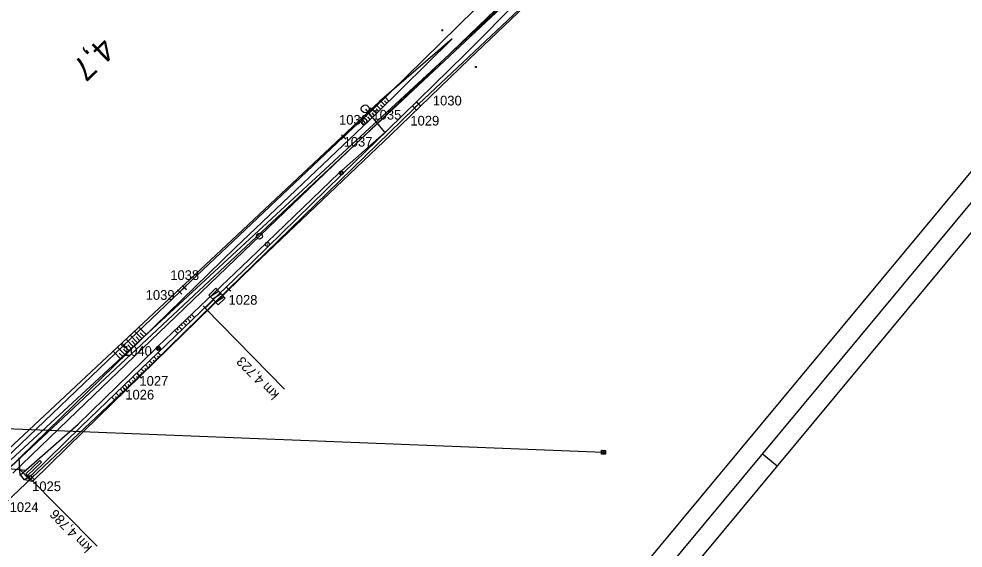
# Model space of a CAD drawing. Extents: x -738085 to -734426, y -1122197 to -1119748.
# Drawn here: x -737687.7 to -737444.6, y -1121801.5 to -1121665.2 of the extents above; entities that cross this region are included whole.
import ezdxf

# ---------------------------------------------------------------- set-up
doc = ezdxf.new("R2010")
doc.units = 0
for name, color, linetype in [('SŽDC', 7, 'Continuous'), ('Vrstva 1', 7, 'Continuous'), ('Vrstva 11', 7, 'Continuous'), ('Vrstva 12', 7, 'Continuous'), ('Vrstva 19', 7, 'Continuous'), ('Vrstva 25', 7, 'Continuous'), ('Vrstva 36', 7, 'Continuous'), ('Vrstva 4', 7, 'Continuous'), ('Vrstva 43', 7, 'Continuous'), ('Vrstva 48', 7, 'Continuous'), ('Vrstva 49', 7, 'Continuous'), ('Vrstva 60', 7, 'Continuous'), ('Vrstva 63', 7, 'Continuous'), ('Vrstva 7', 7, 'Continuous'), ('Vrstva 9', 7, 'Continuous')]:
    doc.layers.add(name, color=color, linetype=linetype)

msp = doc.modelspace()

# ---------------------------------------------------------------- linework, layer by layer
at = {"layer": 'SŽDC'}
for p, q in [((-737585.89, -1121688.17), (-737633.76, -1121734.81)), ((-737599.36, -1121691.09), (-737596.72, -1121688.63)), ((-737604.14, -1121695.61), (-737599.36, -1121691.09)), ((-737645.15, -1121734.39), (-737604.14, -1121695.61)), ((-737633.76, -1121734.81), (-737656.71, -1121757.17)), ((-737696.93, -1121783.83), (-737660.95, -1121749.48)), ((-737684.33, -1121783.29), (-737691.03, -1121789.69))]:
    msp.add_line(p, q, dxfattribs=at)
for points in [[(-737596.72, -1121688.63), (-737552.76, -1121645.44), (-737544, -1121633.28)], [(-737548.98, -1121653.36), (-737584.84, -1121687.15), (-737585.89, -1121688.17)], [(-737660.95, -1121749.48), (-737646.34, -1121735.52), (-737645.15, -1121734.39)], [(-737656.71, -1121757.17), (-737660.35, -1121760.72), (-737684.33, -1121783.29)]]:
    msp.add_lwpolyline(points, dxfattribs=at)
at = {"layer": 'Vrstva 1'}
msp.add_line((-737496.36, -1121777.15), (-737492.52, -1121780.34), dxfattribs=at)
for points in [[(-737452.56, -1121267.51), (-737989.34, -1121913.61), (-737760.91, -1122103.4), (-737224.12, -1121457.29)], [(-737982.3, -1121912.96), (-737451.91, -1121274.55), (-737231.17, -1121457.94), (-737761.56, -1122096.35)], [(-737451.26, -1121281.58), (-737844.27, -1121754.63), (-737631.21, -1121931.64), (-737238.2, -1121458.59)]]:
    msp.add_lwpolyline(points, close=True, dxfattribs=at)
for points in [[(-737505.35, -1121528.98), (-737507.02, -1121535.76), (-737508.18, -1121541.1), (-737509.7, -1121548.87), (-737511.05, -1121556.54), (-737512.45, -1121564.46), (-737514.07, -1121573.14), (-737515.6, -1121580.26), (-737517.59, -1121588.18), (-737519.85, -1121595.56), (-737522.41, -1121602.65), (-737525.26, -1121609.39), (-737528.71, -1121616.54), (-737532.49, -1121623.46), (-737535.97, -1121629.07), (-737539.35, -1121634.1), (-737544.33, -1121640.72), (-737549.2, -1121646.51), (-737554.12, -1121651.88), (-737559.65, -1121657.52), (-737565.05, -1121662.86), (-737573.92, -1121671.42), (-737588.06, -1121684.98)], [(-737505.35, -1121528.98), (-737507.02, -1121535.76), (-737508.18, -1121541.1), (-737509.7, -1121548.87), (-737511.05, -1121556.54), (-737512.45, -1121564.46), (-737514.07, -1121573.14), (-737515.6, -1121580.26), (-737517.59, -1121588.18), (-737519.85, -1121595.56), (-737522.41, -1121602.65), (-737525.26, -1121609.39), (-737528.71, -1121616.54), (-737532.49, -1121623.46), (-737535.97, -1121629.07), (-737539.35, -1121634.1), (-737544.33, -1121640.72), (-737549.2, -1121646.51), (-737554.12, -1121651.88), (-737559.65, -1121657.52), (-737565.05, -1121662.86), (-737573.92, -1121671.42), (-737588.06, -1121684.98)], [(-737588.06, -1121684.98), (-737606.71, -1121702.84), (-737629.82, -1121725.04), (-737653.84, -1121748.12), (-737672.71, -1121766.23), (-737689.31, -1121782.16)], [(-737588.06, -1121684.98), (-737606.71, -1121702.84), (-737629.82, -1121725.04), (-737653.84, -1121748.12), (-737672.71, -1121766.23), (-737689.31, -1121782.16)]]:
    msp.add_lwpolyline(points, dxfattribs=at)
at = {"layer": 'Vrstva 11'}
for p, q in [((-737604.91, -1121704.4), (-737604.93, -1121705.33)), ((-737604.53, -1121704.41), (-737604.55, -1121705.33)), ((-737652.03, -1121749.57), (-737652.05, -1121750.49)), ((-737651.66, -1121749.58), (-737651.68, -1121750.49))]:
    msp.add_line(p, q, dxfattribs=at)
for centre in [(-737604.74, -1121704.87), (-737651.86, -1121750.03)]:
    msp.add_circle(centre, 0.5, dxfattribs=at)
at = {"layer": 'Vrstva 12'}
for p, q in [((-737604.17, -1121704.88), (-737604.75, -1121705.43)), ((-737651.3, -1121750.04), (-737651.88, -1121750.6))]:
    msp.add_line(p, q, dxfattribs=at)
for points in [[(-737605.3, -1121704.85), (-737604.72, -1121704.3), (-737604.17, -1121704.88), (-737604.75, -1121705.43), (-737605.3, -1121704.85)], [(-737605.3, -1121704.85), (-737604.75, -1121705.43), (-737604.75, -1121705.43)], [(-737604.72, -1121704.3), (-737604.17, -1121704.88), (-737604.17, -1121704.88)], [(-737652.43, -1121750.02), (-737651.85, -1121749.47), (-737651.3, -1121750.04), (-737651.88, -1121750.6), (-737652.43, -1121750.02)], [(-737652.43, -1121750.02), (-737651.88, -1121750.6), (-737651.88, -1121750.6)], [(-737651.85, -1121749.47), (-737651.3, -1121750.04), (-737651.3, -1121750.04)]]:
    msp.add_lwpolyline(points, dxfattribs=at)
at = {"layer": 'Vrstva 19'}
msp.add_line((-737593.58, -1121694.27), (-737598.4, -1121688.46), dxfattribs=at)
at = {"layer": 'Vrstva 25'}
msp.add_line((-737796.88, -1121766.52), (-737537.22, -1121776.8), dxfattribs=at)
at = {"layer": 'Vrstva 36'}
for p, q in [((-737536.81, -1121776.31), (-737537.73, -1121777.16)), ((-737537.38, -1121776.29), (-737537.71, -1121776.6)), ((-737536.72, -1121776.77), (-737537.29, -1121777.29))]:
    msp.add_line(p, q, dxfattribs=at)
msp.add_lwpolyline([(-737536.74, -1121777.32), (-737537.74, -1121777.28), (-737537.7, -1121776.28), (-737536.7, -1121776.32), (-737536.74, -1121777.32)], dxfattribs=at)
at = {"layer": 'Vrstva 4'}
for p, q in [((-737687.37, -1121782.83), (-737687.63, -1121778.23)), ((-737690.51, -1121781), (-737685.93, -1121781.44)), ((-737685.02, -1121783.83), (-737687.44, -1121781.31)), ((-737685.38, -1121784.18), (-737684.66, -1121783.48))]:
    msp.add_line(p, q, dxfattribs=at)
at = {"layer": 'Vrstva 43'}
msp.add_circle((-737598.58, -1121688.37), 1, dxfattribs=at)
at = {"layer": 'Vrstva 48'}
for p, q in [((-737593.55, -1121687.42), (-737594.69, -1121686.25)), ((-737593.01, -1121686.9), (-737593.57, -1121686.33)), ((-737592.47, -1121686.37), (-737593.55, -1121685.27)), ((-737596.77, -1121690.56), (-737597.96, -1121689.31)), ((-737595.69, -1121689.53), (-737596.89, -1121688.3)), ((-737596.23, -1121690.04), (-737596.82, -1121689.42)), ((-737594.61, -1121688.48), (-737595.8, -1121687.27)), ((-737595.15, -1121689), (-737595.75, -1121688.39)), ((-737594.08, -1121687.95), (-737594.67, -1121687.35)), ((-737598.95, -1121692.63), (-737600.14, -1121691.37)), ((-737597.86, -1121691.59), (-737599.05, -1121690.34)), ((-737598.4, -1121692.11), (-737599, -1121691.48)), ((-737597.32, -1121691.08), (-737597.91, -1121690.45)), ((-737644.9, -1121742.85), (-737644.53, -1121743.25)), ((-737644.36, -1121742.34), (-737643.61, -1121743.13)), ((-737643.82, -1121741.82), (-737643.44, -1121742.22)), ((-737643.27, -1121741.3), (-737642.53, -1121742.09)), ((-737655.01, -1121746.51), (-737656.86, -1121744.61)), ((-737647.08, -1121744.92), (-737646.69, -1121745.33)), ((-737646.53, -1121744.41), (-737645.77, -1121745.21)), ((-737645.99, -1121743.89), (-737645.61, -1121744.29)), ((-737645.45, -1121743.37), (-737644.69, -1121744.17)), ((-737658.23, -1121749.65), (-737660.15, -1121747.68)), ((-737657.16, -1121748.6), (-737659.06, -1121746.66)), ((-737656.08, -1121747.55), (-737657.96, -1121745.63)), ((-737656.62, -1121748.08), (-737657.57, -1121747.11)), ((-737655.55, -1121747.03), (-737656.48, -1121746.08)), ((-737647.62, -1121745.44), (-737646.85, -1121746.25)), ((-737660.38, -1121751.75), (-737662.35, -1121749.73)), ((-737659.31, -1121750.7), (-737661.25, -1121748.71)), ((-737659.84, -1121751.22), (-737660.82, -1121750.22)), ((-737658.77, -1121750.17), (-737659.73, -1121749.18)), ((-737657.7, -1121749.13), (-737658.65, -1121748.15)), ((-737661.45, -1121752.79), (-737663.44, -1121750.75)), ((-737660.92, -1121752.27), (-737661.91, -1121751.26)), ((-737652.19, -1121753.02), (-737653.01, -1121752.18)), ((-737651.66, -1121752.5), (-737652.06, -1121752.08)), ((-737651.12, -1121751.97), (-737651.93, -1121751.14)), ((-737654.34, -1121755.12), (-737655.17, -1121754.26)), ((-737653.8, -1121754.59), (-737654.22, -1121754.17)), ((-737653.26, -1121754.07), (-737654.09, -1121753.22)), ((-737652.73, -1121753.54), (-737653.14, -1121753.12)), ((-737657.55, -1121758.26), (-737658.41, -1121757.38)), ((-737657.02, -1121757.74), (-737657.45, -1121757.3)), ((-737656.48, -1121757.21), (-737657.33, -1121756.34)), ((-737655.95, -1121756.69), (-737656.37, -1121756.26)), ((-737655.41, -1121756.17), (-737656.25, -1121755.3)), ((-737654.87, -1121755.64), (-737655.29, -1121755.21)), ((-737659.7, -1121760.36), (-737660.58, -1121759.46)), ((-737659.16, -1121759.83), (-737659.6, -1121759.39)), ((-737658.63, -1121759.31), (-737659.49, -1121758.42)), ((-737658.09, -1121758.79), (-737658.52, -1121758.34)), ((-737661.84, -1121762.46), (-737662.74, -1121761.54)), ((-737661.31, -1121761.93), (-737661.75, -1121761.48)), ((-737660.77, -1121761.41), (-737661.66, -1121760.5)), ((-737660.24, -1121760.88), (-737660.68, -1121760.43)), ((-737662.92, -1121763.51), (-737663.82, -1121762.58)), ((-737662.38, -1121762.98), (-737662.83, -1121762.52))]:
    msp.add_line(p, q, dxfattribs=at)
at = {"layer": 'Vrstva 49'}
for p, q in [((-737578.48, -1121668.16), (-737578.98, -1121668.15)), ((-737578.72, -1121667.9), (-737578.73, -1121668.4)), ((-737569.81, -1121677.61), (-737570.31, -1121677.6)), ((-737570.06, -1121677.35), (-737570.07, -1121677.85))]:
    msp.add_line(p, q, dxfattribs=at)
for points in [[(-737537.78, -1121634.82), (-737536.39, -1121635.05), (-737535.35, -1121636.97), (-737550.38, -1121655.07), (-737571.7, -1121675.53), (-737591.99, -1121695.03), (-737627.26, -1121728.64), (-737670.99, -1121771.4), (-737684.23, -1121784.32), (-737686.26, -1121783.92), (-737687.29, -1121782.58)], [(-737537.78, -1121634.82), (-737537.57, -1121635.74), (-737536.9, -1121636.24), (-737537.4, -1121636.9), (-737537.63, -1121637.32), (-737551.7, -1121653.77), (-737557.57, -1121658.88), (-737558.15, -1121659.48), (-737572.93, -1121674.36), (-737592.85, -1121693.86), (-737604.17, -1121704.88), (-737604.75, -1121705.43), (-737627.7, -1121727.82), (-737671.73, -1121770.2), (-737684.57, -1121782.83), (-737686.26, -1121783.92)], [(-737576.15, -1121670.34), (-737594.92, -1121686.44), (-737634.25, -1121723.48), (-737693.22, -1121778.57), (-737695.95, -1121780.13)], [(-737695.95, -1121780.13), (-737693.1, -1121781.63), (-737690.77, -1121781.4), (-737632.01, -1121724.06), (-737595.71, -1121689.55), (-737576.15, -1121670.34)], [(-737687.29, -1121782.58), (-737672.48, -1121769.55), (-737652.43, -1121750.02), (-737651.85, -1121749.47), (-737628.41, -1121727.15), (-737605.3, -1121704.85), (-737604.72, -1121704.3), (-737592.85, -1121693.86)]]:
    msp.add_lwpolyline(points, dxfattribs=at)
at = {"layer": 'Vrstva 60'}
for p, q in [((-737584.39, -1121687.6), (-737585.39, -1121686.6)), ((-737584.39, -1121686.7), (-737585.39, -1121687.7)), ((-737585.29, -1121687.6), (-737584.29, -1121686.6)), ((-737585.29, -1121686.7), (-737584.29, -1121687.7)), ((-737596.27, -1121689.08), (-737597.27, -1121688.08)), ((-737596.27, -1121688.18), (-737597.27, -1121689.18)), ((-737597.17, -1121689.08), (-737596.17, -1121688.08)), ((-737597.17, -1121688.18), (-737596.17, -1121689.18)), ((-737596.72, -1121688.63), (-737596.72, -1121688.63)), ((-737585.44, -1121688.62), (-737586.44, -1121687.62)), ((-737585.44, -1121687.72), (-737586.44, -1121688.72)), ((-737586.34, -1121688.62), (-737585.34, -1121687.62)), ((-737586.34, -1121687.72), (-737585.34, -1121688.72)), ((-737585.89, -1121688.17), (-737585.89, -1121688.17)), ((-737584.84, -1121687.15), (-737584.84, -1121687.15)), ((-737598.91, -1121691.54), (-737599.91, -1121690.54)), ((-737598.91, -1121690.64), (-737599.91, -1121691.64)), ((-737599.81, -1121691.54), (-737598.81, -1121690.54)), ((-737599.81, -1121690.64), (-737598.81, -1121691.64)), ((-737599.36, -1121691.09), (-737599.36, -1121691.09)), ((-737603.69, -1121696.06), (-737604.69, -1121695.06)), ((-737603.69, -1121695.16), (-737604.69, -1121696.16)), ((-737604.59, -1121696.06), (-737603.59, -1121695.06)), ((-737604.59, -1121695.16), (-737603.59, -1121696.16)), ((-737604.14, -1121695.61), (-737604.14, -1121695.61)), ((-737645.89, -1121735.97), (-737646.89, -1121734.97)), ((-737645.89, -1121735.07), (-737646.89, -1121736.07)), ((-737646.79, -1121735.97), (-737645.79, -1121734.97)), ((-737646.79, -1121735.07), (-737645.79, -1121736.07)), ((-737646.34, -1121735.52), (-737646.34, -1121735.52)), ((-737644.7, -1121734.84), (-737645.7, -1121733.84)), ((-737644.7, -1121733.94), (-737645.7, -1121734.94)), ((-737645.6, -1121734.84), (-737644.6, -1121733.84)), ((-737645.6, -1121733.94), (-737644.6, -1121734.94)), ((-737645.15, -1121734.39), (-737645.15, -1121734.39)), ((-737633.31, -1121735.26), (-737634.31, -1121734.26)), ((-737633.31, -1121734.36), (-737634.31, -1121735.36)), ((-737634.21, -1121735.26), (-737633.21, -1121734.26)), ((-737634.21, -1121734.36), (-737633.21, -1121735.36)), ((-737633.76, -1121734.81), (-737633.76, -1121734.81)), ((-737660.5, -1121749.93), (-737661.5, -1121748.93)), ((-737660.5, -1121749.03), (-737661.5, -1121750.03)), ((-737661.4, -1121749.93), (-737660.4, -1121748.93)), ((-737661.4, -1121749.03), (-737660.4, -1121750.03)), ((-737660.95, -1121749.48), (-737660.95, -1121749.48)), ((-737656.26, -1121757.62), (-737657.26, -1121756.62)), ((-737656.26, -1121756.72), (-737657.26, -1121757.72)), ((-737657.16, -1121757.62), (-737656.16, -1121756.62)), ((-737657.16, -1121756.72), (-737656.16, -1121757.72)), ((-737656.71, -1121757.17), (-737656.71, -1121757.17)), ((-737659.9, -1121761.17), (-737660.9, -1121760.17)), ((-737659.9, -1121760.27), (-737660.9, -1121761.27)), ((-737660.8, -1121761.17), (-737659.8, -1121760.17)), ((-737660.8, -1121760.27), (-737659.8, -1121761.27)), ((-737660.35, -1121760.72), (-737660.35, -1121760.72)), ((-737683.88, -1121783.74), (-737684.88, -1121782.74)), ((-737683.88, -1121782.84), (-737684.88, -1121783.84)), ((-737684.78, -1121783.74), (-737683.78, -1121782.74)), ((-737684.78, -1121782.84), (-737683.78, -1121783.84)), ((-737684.33, -1121783.29), (-737684.33, -1121783.29))]:
    msp.add_line(p, q, dxfattribs=at)
at = {"layer": 'Vrstva 63'}
for p in [(-737696.42, -1121784.79), (-737691.07, -1121781.8)]:
    msp.add_line(p, (-737530.36, -1121631.2), dxfattribs=at)
at = {"layer": 'Vrstva 7'}
for p, q in [((-737623.75, -1121723.23), (-737623.82, -1121723.3)), ((-737638.48, -1121736.68), (-737636.33, -1121735.31)), ((-737635.64, -1121736.03), (-737637.79, -1121737.4)), ((-737637.1, -1121738.12), (-737634.95, -1121736.75)), ((-737640.3, -1121739.11), (-737639.26, -1121740.2)), ((-737639.78, -1121739.66), (-737619.39, -1121760.6))]:
    msp.add_line(p, q, dxfattribs=at)
msp.add_lwpolyline([(-737639.78, -1121739.66), (-737637.62, -1121737.58), (-737636.41, -1121738.84), (-737634.6, -1121737.11), (-737637.03, -1121734.58), (-737638.83, -1121736.32), (-737637.62, -1121737.58)], dxfattribs=at)
for centre, radius in [((-737625.8, -1121721.17), 0.75), ((-737625.8, -1121721.17), 0.75), ((-737623.78, -1121723.27), 0.5)]:
    msp.add_circle(centre, radius, dxfattribs=at)
at = {"layer": 'Vrstva 9'}
for p, q in [((-737682.34, -1121778.94), (-737685.94, -1121782.4)), ((-737685.53, -1121782.83), (-737681.92, -1121779.37)), ((-737681.92, -1121779.37), (-737682.34, -1121778.94)), ((-737685.94, -1121782.4), (-737685.53, -1121782.83)), ((-737685.74, -1121782.62), (-737667.55, -1121801.01)), ((-737685.53, -1121782.83), (-737685.11, -1121783.27))]:
    msp.add_line(p, q, dxfattribs=at)

# ---------------------------------------------------------------- texts
at = {"layer": 'Vrstva 60'}
for s, p in [('1030', (-737581.16, -1121687.5)), ('1035', (-737596.72, -1121691.13)), ('1036', (-737605.31, -1121692.44)), ('1029', (-737586.95, -1121692.67)), ('1037', (-737604.14, -1121698.11)), ('1038', (-737648.77, -1121732.44)), ('1039', (-737655.09, -1121737.55)), ('1028', (-737633.76, -1121738.81)), ('1040', (-737660.95, -1121751.98)), ('1027', (-737656.71, -1121759.67)), ('1026', (-737660.35, -1121763.22)), ('1025', (-737684.33, -1121786.82)), ('1024', (-737690.12, -1121792.19))]:
    msp.add_text(s, height=2.5, dxfattribs=at).set_placement(p)
at = {"layer": 'Vrstva 7'}
for s, height, rotation, p in [('4,7', 6, 223.8356, (-737666.49, -1121669.56)), ('4,7', 6, 223.8356, (-737666.49, -1121669.56)), ('km 4,723', 2.5, 134.2336, (-737620.58, -1121761.79))]:
    msp.add_text(s, height=height, rotation=rotation, dxfattribs=at).set_placement(p)
at = {"layer": 'Vrstva 9'}
msp.add_text('km 4,786', height=2.5, rotation=133.8253, dxfattribs=at).set_placement((-737668.71, -1121801.2))

doc.saveas('drawing.dxf')
